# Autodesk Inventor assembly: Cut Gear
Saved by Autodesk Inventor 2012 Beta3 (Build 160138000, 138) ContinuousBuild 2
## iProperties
Created: 2011-01
Part Number: Cut Gear
Document SubType Name: Assembly
Designer: Beta-8540w
Categories: <?xml version="1.0" encoding="UTF-16"?> <MemberInstance><Categories><FamilyTemplate/><ParamToTemplateMap><ParamToTemplate><ParamToTemplate CategoryParameter="//
ClientObjectVersion: 1
Author: Beta-8540w
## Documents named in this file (1)
- C:\Inventor 2012 Essentials\Assemblies\Chapter 8\Design Accelerators\Cut Gear c08-02.iam
